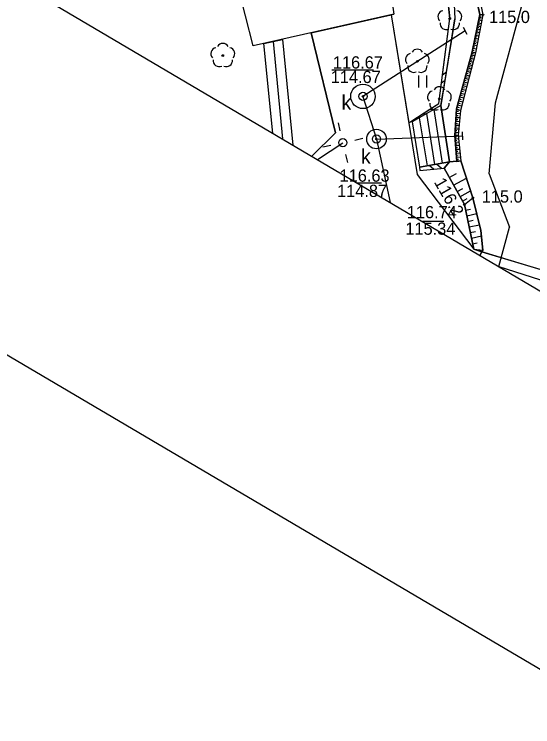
# Model space of a CAD drawing. Extents: x 6434771 to 6436222, y 5663454 to 5664782.
# Drawn here: x 6434897.1 to 6434928.91, y 5663961.14 to 5664004.88 of the extents above; entities that cross this region are included whole.
import ezdxf

# ---------------------------------------------------------------- set-up
doc = ezdxf.new("R2010")
doc.units = 0
for name, color, linetype in [('Warstwa 1', 7, 'Continuous'), ('Warstwa 11', 7, 'Continuous'), ('Warstwa 12', 7, 'Continuous'), ('Warstwa 13', 7, 'Continuous'), ('Warstwa 14', 7, 'Continuous'), ('Warstwa 15', 7, 'Continuous'), ('Warstwa 2', 7, 'Continuous'), ('Warstwa 20', 7, 'Continuous'), ('Warstwa 21', 7, 'Continuous'), ('Warstwa 36', 7, 'Continuous'), ('Warstwa 4', 7, 'Continuous'), ('Warstwa 5', 7, 'Continuous'), ('Warstwa 51', 7, 'Continuous'), ('Warstwa 6', 7, 'Continuous'), ('Warstwa 63', 7, 'Continuous'), ('Warstwa 7', 7, 'Continuous'), ('Warstwa 8', 7, 'Continuous'), ('Warstwa 9', 7, 'Continuous')]:
    doc.layers.add(name, color=color, linetype=linetype)

msp = doc.modelspace()

# ---------------------------------------------------------------- linework, layer by layer
at = {"layer": 'Warstwa 1'}
for p, q in [((6434926.635, 5663999.433), (6434928.362, 5664005.889)), ((6434926.235, 5663995.079), (6434926.635, 5663999.433)), ((6434926.235, 5663995.079), (6434927.494, 5663991.812)), ((6434926.828, 5663989.395), (6434927.494, 5663991.812))]:
    msp.add_line(p, q, dxfattribs=at)
msp.add_lwpolyline([(6434911.812, 5664031.828), (6434920.38, 5664029.894), (6434918.982, 5664020.154), (6434921.832, 5664020.166), (6434921.856, 5664014.645), (6434919.005, 5664014.634), (6434920.397, 5664004.883), (6434911.753, 5664002.928), (6434910.828, 5664006.639), (6434910.117, 5664010.758), (6434909.494, 5664014.626), (6434909.488, 5664017.416), (6434909.44, 5664020.046), (6434910.163, 5664023.638), (6434910.979, 5664028.218)], close=True, dxfattribs=at)
at = {"layer": 'Warstwa 11'}
msp.add_lwpolyline([(6434925.122, 5664008.575), (6434925.857, 5664004.846), (6434925.409, 5664002.512), (6434924.476, 5663998.973), (6434924.338, 5663997.464), (6434924.499, 5663995.882), (6434925.241, 5663993.613), (6434925.737, 5663991.597), (6434925.843, 5663990.406), (6434925.787, 5663990.299), (6434925.671, 5663990.077)], dxfattribs=at)
for centre in [(6434923.824, 5664004.611), (6434909.896, 5664002.34), (6434921.832, 5664001.985), (6434923.185, 5663999.678)]:
    msp.add_circle(centre, 0.05, dxfattribs=at)
for centre, start, end in [((6434923.467, 5664004.727), 102.1471, 221.8529), ((6434924.181, 5664004.727), 318.1471, 77.8529), ((6434923.604, 5664004.308), 174.1471, 293.8529), ((6434924.044, 5664004.308), 246.1471, 5.8529), ((6434909.896, 5664002.715), 30.1471, 149.8529), ((6434909.539, 5664002.456), 102.1471, 221.8529), ((6434910.253, 5664002.456), 318.1471, 77.8529), ((6434921.832, 5664002.36), 30.1471, 149.8529), ((6434909.676, 5664002.037), 174.1471, 293.8529), ((6434910.116, 5664002.037), 246.1471, 5.8529), ((6434921.475, 5664002.101), 102.1471, 221.8529), ((6434922.189, 5664002.101), 318.1471, 77.8529), ((6434921.612, 5664001.682), 174.1471, 293.8529), ((6434922.052, 5664001.682), 246.1471, 5.8529), ((6434923.185, 5664000.053), 30.1471, 149.8529), ((6434922.828, 5663999.794), 102.1471, 221.8529), ((6434923.542, 5663999.794), 318.1471, 77.8529), ((6434922.965, 5663999.375), 174.1471, 293.8529), ((6434923.405, 5663999.375), 246.1471, 5.8529)]:
    msp.add_arc(centre, 0.375, start, end, dxfattribs=at)
at = {"layer": 'Warstwa 12'}
for points in [[(6434912.982, 5664003.206), (6434913.556, 5663997.226)], [(6434915.706, 5663995.958), (6434917.262, 5663996.99)]]:
    msp.add_lwpolyline(points, dxfattribs=at)
at = {"layer": 'Warstwa 13'}
for centre in [(6434925.857, 5664004.846), (6434925.241, 5663993.613), (6434924.716, 5663993.19)]:
    msp.add_circle(centre, 0.045, dxfattribs=at)
at = {"layer": 'Warstwa 14'}
for p, q in [((6434919.142, 5664001.452), (6434916.593, 5664001.452)), ((6434919.641, 5663994.508), (6434918.162, 5663994.508)), ((6434923.463, 5663992.147), (6434922.164, 5663992.147))]:
    msp.add_line(p, q, dxfattribs=at)
for centre in [(6434918.496, 5663999.835), (6434919.324, 5663997.215)]:
    msp.add_circle(centre, 0.045, dxfattribs=at)
at = {"layer": 'Warstwa 15'}
for centre, radius in [((6434918.496, 5663999.835), 0.75), ((6434919.324, 5663997.215), 0.6)]:
    msp.add_circle(centre, radius, dxfattribs=at)
at = {"layer": 'Warstwa 2'}
for points in [[(6434920.236, 5664004.847), (6434921.818, 5663995.035), (6434925.293, 5663990.452), (6434938.635, 5663986.4)], [(6434915.352, 5663996.166), (6434916.809, 5663997.596), (6434915.318, 5664003.734)]]:
    msp.add_lwpolyline(points, dxfattribs=at)
msp.add_circle((6434917.262, 5663996.99), 0.25, dxfattribs=at)
at = {"layer": 'Warstwa 20'}
for p, q in [((6434924.889, 5664003.626), (6434924.661, 5664004.072)), ((6434924.618, 5663997.161), (6434924.596, 5663997.661))]:
    msp.add_line(p, q, dxfattribs=at)
for points in [[(6434925.546, 5664033.621), (6434924.451, 5664030.734), (6434923.907, 5664028.791), (6434923.383, 5664023.537), (6434924.334, 5664011.185), (6434924.872, 5664008.518), (6434925.668, 5664004.869), (6434925.2, 5664002.574), (6434924.237, 5663999.066), (6434924.128, 5663997.437), (6434924.248, 5663995.845)], [(6434925.293, 5663990.452), (6434924.716, 5663993.19), (6434923.473, 5663995.425)]]:
    msp.add_lwpolyline(points, dxfattribs=at)
at = {"layer": 'Warstwa 21'}
for points in [[(6434925.755, 5664033.559), (6434924.242, 5664028.377), (6434923.988, 5664023.91), (6434923.741, 5664023.373), (6434924.496, 5664011.353), (6434925.122, 5664008.575), (6434925.857, 5664004.846), (6434925.409, 5664002.512), (6434924.476, 5663998.973), (6434924.338, 5663997.464), (6434924.499, 5663995.882)], [(6434924.499, 5663995.882), (6434925.241, 5663993.613), (6434925.737, 5663991.597), (6434925.843, 5663990.406), (6434925.787, 5663990.299)]]:
    msp.add_lwpolyline(points, dxfattribs=at)
at = {"layer": 'Warstwa 36'}
for p, q in [((6434922.837, 5663999.028), (6434923.347, 5663995.736)), ((6434922.394, 5663998.778), (6434922.886, 5663995.652)), ((6434921.951, 5663998.528), (6434922.425, 5663995.567))]:
    msp.add_line(p, q, dxfattribs=at)
msp.add_lwpolyline([(6434923.28, 5663999.277), (6434921.508, 5663998.279), (6434921.964, 5663995.483), (6434923.808, 5663995.821), (6434923.28, 5663999.277)], dxfattribs=at)
at = {"layer": 'Warstwa 4'}
for points in [[(6434917.096, 5663997.721), (6434916.986, 5663998.209)], [(6434917.993, 5663997.156), (6434918.481, 5663997.266)], [(6434916.531, 5663996.824), (6434916.043, 5663996.714)], [(6434917.428, 5663996.259), (6434917.538, 5663995.771)]]:
    msp.add_lwpolyline(points, dxfattribs=at)
for centre in [(6434918.496, 5663999.835), (6434919.324, 5663997.215)]:
    msp.add_circle(centre, 0.25, dxfattribs=at)
at = {"layer": 'Warstwa 5'}
for p, q in [((6434924.872, 5664008.518), (6434925.668, 5664004.869)), ((6434924.041, 5664006.623), (6434924.134, 5664004.587)), ((6434923.661, 5664006.154), (6434923.824, 5664004.611)), ((6434920.236, 5664004.847), (6434920.397, 5664004.883)), ((6434920.236, 5664004.847), (6434921.307, 5663998.202)), ((6434925.2, 5664002.574), (6434925.668, 5664004.869)), ((6434923.371, 5664001.151), (6434923.824, 5664004.611)), ((6434923.611, 5664001.335), (6434924.134, 5664004.587)), ((6434924.237, 5663999.066), (6434925.2, 5664002.574)), ((6434923.53, 5664000.832), (6434923.611, 5664001.335)), ((6434921.916, 5664000.371), (6434921.916, 5664001.121)), ((6434922.416, 5664000.371), (6434922.416, 5664001.121)), ((6434923.28, 5663999.277), (6434923.53, 5664000.832)), ((6434923.306, 5664000.66), (6434923.371, 5664001.151)), ((6434923.141, 5663999.399), (6434923.306, 5664000.66)), ((6434921.488, 5663998.339), (6434922.608, 5663999.057)), ((6434922.608, 5663999.057), (6434923.141, 5663999.399)), ((6434923.28, 5663999.277), (6434923.808, 5663995.821)), ((6434924.128, 5663997.437), (6434924.237, 5663999.066)), ((6434921.307, 5663998.202), (6434921.488, 5663998.339)), ((6434924.128, 5663997.437), (6434924.247, 5663995.86)), ((6434923.808, 5663995.821), (6434924.247, 5663995.86))]:
    msp.add_line(p, q, dxfattribs=at)
at = {"layer": 'Warstwa 51'}
for p, q in [((6434923.37, 5664001.151), (6434923.611, 5664001.335)), ((6434923.306, 5664000.66), (6434923.53, 5664000.832)), ((6434922.608, 5663999.057), (6434922.811, 5663999.013)), ((6434922.192, 5663998.789), (6434922.352, 5663998.755)), ((6434922.824, 5663995.363), (6434922.549, 5663995.59)), ((6434923.317, 5663995.41), (6434922.999, 5663995.673))]:
    msp.add_line(p, q, dxfattribs=at)
for points in [[(6434921.488, 5663998.339), (6434923.141, 5663999.399), (6434923.824, 5664004.611), (6434923.142, 5664011.06), (6434923.107, 5664014.77), (6434922.7, 5664021.635), (6434922.646, 5664022.146), (6434922.795, 5664023.654), (6434923.613, 5664011.124), (6434923.952, 5664008.56), (6434924.134, 5664004.587), (6434923.28, 5663999.277), (6434921.508, 5663998.279), (6434921.488, 5663998.339)], [(6434923.473, 5663995.425), (6434923.808, 5663995.821), (6434921.964, 5663995.483), (6434921.981, 5663995.283), (6434923.473, 5663995.425)]]:
    msp.add_lwpolyline(points, dxfattribs=at)
at = {"layer": 'Warstwa 6'}
for centre in [(6434918.496, 5663999.835), (6434919.324, 5663997.215)]:
    msp.add_circle(centre, 0.045, dxfattribs=at)
at = {"layer": 'Warstwa 63'}
for points in [[(6434770.578, 5664058.35), (6435197.816, 5664782.406), (6436221.837, 5664178.169), (6435794.599, 5663454.114)], [(6435677.2, 5663546.629), (6436084.093, 5664236.205), (6435222.122, 5664744.822), (6434815.229, 5664055.245)]]:
    msp.add_lwpolyline(points, close=True, dxfattribs=at)
at = {"layer": 'Warstwa 7'}
for points in [[(6434924.775, 5664003.849), (6434918.496, 5663999.835), (6434919.324, 5663997.215)], [(6434919.324, 5663997.215), (6434924.607, 5663997.411)], [(6434919.324, 5663997.215), (6434920.162, 5663993.328)]]:
    msp.add_lwpolyline(points, dxfattribs=at)
at = {"layer": 'Warstwa 8'}
for points in [[(6434912.957, 5663997.579), (6434912.407, 5664003.076), (6434913.558, 5664003.336), (6434914.203, 5663996.844)], [(6434926.834, 5663989.391), (6434930.863, 5663988.105), (6434943.667, 5663984.044), (6434942.349, 5663980.236)]]:
    msp.add_lwpolyline(points, dxfattribs=at)
at = {"layer": 'Warstwa 9'}
for p, q in [((6434915.318, 5664003.734), (6434920.236, 5664004.847)), ((6434920.236, 5664004.847), (6434921.818, 5663995.035)), ((6434925.633, 5664004.698), (6434925.821, 5664004.66)), ((6434925.651, 5664004.784), (6434925.744, 5664004.765)), ((6434925.857, 5664004.846), (6434925.668, 5664004.869)), ((6434925.668, 5664004.869), (6434925.857, 5664004.846)), ((6434925.543, 5664004.256), (6434925.64, 5664004.237)), ((6434925.561, 5664004.347), (6434925.754, 5664004.307)), ((6434925.579, 5664004.436), (6434925.675, 5664004.416)), ((6434925.597, 5664004.524), (6434925.788, 5664004.485)), ((6434925.616, 5664004.611), (6434925.71, 5664004.592)), ((6434925.448, 5664003.791), (6434925.647, 5664003.751)), ((6434925.468, 5664003.887), (6434925.567, 5664003.867)), ((6434925.487, 5664003.981), (6434925.683, 5664003.94)), ((6434925.506, 5664004.073), (6434925.604, 5664004.053)), ((6434925.524, 5664004.165), (6434925.719, 5664004.126)), ((6434915.318, 5664003.734), (6434916.809, 5663997.596)), ((6434925.369, 5664003.402), (6434925.572, 5664003.361)), ((6434925.389, 5664003.501), (6434925.49, 5664003.481)), ((6434925.409, 5664003.599), (6434925.61, 5664003.558)), ((6434925.428, 5664003.695), (6434925.528, 5664003.675)), ((6434925.286, 5664002.997), (6434925.494, 5664002.955)), ((6434925.307, 5664003.1), (6434925.411, 5664003.079)), ((6434925.327, 5664003.202), (6434925.534, 5664003.159)), ((6434925.349, 5664003.302), (6434925.45, 5664003.281)), ((6434925.174, 5664002.479), (6434925.279, 5664002.45)), ((6434925.2, 5664002.574), (6434925.409, 5664002.512)), ((6434925.222, 5664002.681), (6434925.328, 5664002.66)), ((6434925.243, 5664002.788), (6434925.454, 5664002.745)), ((6434925.265, 5664002.892), (6434925.369, 5664002.871)), ((6434925.067, 5664002.091), (6434925.175, 5664002.061)), ((6434925.094, 5664002.189), (6434925.308, 5664002.131)), ((6434925.121, 5664002.287), (6434925.228, 5664002.258)), ((6434925.148, 5664002.384), (6434925.36, 5664002.325)), ((6434924.957, 5664001.687), (6434925.067, 5664001.658)), ((6434924.984, 5664001.79), (6434925.203, 5664001.73)), ((6434925.013, 5664001.891), (6434925.121, 5664001.861)), ((6434925.04, 5664001.991), (6434925.256, 5664001.931)), ((6434924.813, 5664001.163), (6434925.037, 5664001.101)), ((6434924.842, 5664001.269), (6434924.954, 5664001.239)), ((6434924.871, 5664001.375), (6434925.094, 5664001.314)), ((6434924.9, 5664001.481), (6434925.01, 5664001.45)), ((6434924.928, 5664001.584), (6434925.149, 5664001.524)), ((6434924.692, 5664000.725), (6434924.922, 5664000.662)), ((6434924.723, 5664000.837), (6434924.837, 5664000.805)), ((6434924.753, 5664000.946), (6434924.98, 5664000.884)), ((6434924.783, 5664001.055), (6434924.896, 5664001.024)), ((6434924.6, 5664000.387), (6434924.716, 5664000.356)), ((6434924.631, 5664000.501), (6434924.862, 5664000.437)), ((6434924.662, 5664000.614), (6434924.777, 5664000.582)), ((6434924.473, 5663999.922), (6434924.59, 5663999.889)), ((6434924.504, 5664000.039), (6434924.74, 5663999.975)), ((6434924.537, 5664000.157), (6434924.654, 5664000.125)), ((6434924.568, 5664000.273), (6434924.802, 5664000.209)), ((6434924.34, 5663999.439), (6434924.46, 5663999.406)), ((6434924.373, 5663999.562), (6434924.615, 5663999.496)), ((6434924.407, 5663999.683), (6434924.526, 5663999.65)), ((6434924.439, 5663999.803), (6434924.677, 5663999.737)), ((6434924.237, 5663999.066), (6434924.476, 5663998.973)), ((6434924.272, 5663999.192), (6434924.394, 5663999.159)), ((6434924.306, 5663999.316), (6434924.55, 5663999.249)), ((6434924.202, 5663998.546), (6434924.436, 5663998.53)), ((6434924.211, 5663998.671), (6434924.328, 5663998.664)), ((6434924.219, 5663998.799), (6434924.459, 5663998.783)), ((6434924.229, 5663998.93), (6434924.35, 5663998.922)), ((6434924.178, 5663998.187), (6434924.291, 5663998.18)), ((6434924.186, 5663998.304), (6434924.414, 5663998.288)), ((6434924.195, 5663998.423), (6434924.309, 5663998.416)), ((6434924.148, 5663997.745), (6434924.255, 5663997.737)), ((6434924.156, 5663997.852), (6434924.372, 5663997.837)), ((6434924.163, 5663997.96), (6434924.273, 5663997.953)), ((6434924.17, 5663998.072), (6434924.392, 5663998.058)), ((6434915.352, 5663996.166), (6434916.809, 5663997.596)), ((6434924.128, 5663997.437), (6434924.338, 5663997.464)), ((6434924.135, 5663997.538), (6434924.239, 5663997.531)), ((6434924.135, 5663997.338), (6434924.242, 5663997.346)), ((6434924.141, 5663997.64), (6434924.353, 5663997.625)), ((6434924.143, 5663997.238), (6434924.359, 5663997.254)), ((6434924.151, 5663997.135), (6434924.26, 5663997.143)), ((6434924.159, 5663997.031), (6434924.38, 5663997.047)), ((6434924.166, 5663996.923), (6434924.278, 5663996.932)), ((6434924.175, 5663996.813), (6434924.402, 5663996.831)), ((6434924.184, 5663996.702), (6434924.299, 5663996.711)), ((6434924.192, 5663996.587), (6434924.426, 5663996.604)), ((6434924.201, 5663996.47), (6434924.319, 5663996.48)), ((6434924.21, 5663996.351), (6434924.45, 5663996.369)), ((6434924.219, 5663996.229), (6434924.34, 5663996.238)), ((6434924.228, 5663996.104), (6434924.475, 5663996.123)), ((6434924.239, 5663995.976), (6434924.363, 5663995.986)), ((6434924.499, 5663995.882), (6434923.808, 5663995.821)), ((6434924.248, 5663995.845), (6434924.499, 5663995.882)), ((6434923.792, 5663994.851), (6434924.234, 5663995.096)), ((6434921.818, 5663995.035), (6434925.293, 5663990.452)), ((6434924.055, 5663994.379), (6434924.847, 5663994.819)), ((6434924.271, 5663993.99), (6434924.629, 5663994.19)), ((6434924.449, 5663993.67), (6434925.103, 5663994.034)), ((6434924.596, 5663993.406), (6434924.898, 5663993.573)), ((6434924.716, 5663993.19), (6434925.241, 5663993.613)), ((6434924.788, 5663992.849), (6434925.093, 5663992.913)), ((6434924.86, 5663992.507), (6434925.482, 5663992.637)), ((6434924.933, 5663992.164), (6434925.249, 5663992.231)), ((6434925.005, 5663991.822), (6434925.648, 5663991.957)), ((6434925.077, 5663991.479), (6434925.404, 5663991.548)), ((6434925.148, 5663991.137), (6434925.766, 5663991.268)), ((6434925.221, 5663990.794), (6434925.509, 5663990.855)), ((6434925.293, 5663990.452), (6434925.843, 5663990.406)), ((6434925.293, 5663990.452), (6434925.788, 5663990.302)), ((6434925.67, 5663990.078), (6434925.788, 5663990.302)), ((6434925.671, 5663990.077), (6434925.787, 5663990.299)), ((6434925.787, 5663990.299), (6434938.424, 5663986.464))]:
    msp.add_line(p, q, dxfattribs=at)
for points in [[(6434924.248, 5663995.845), (6434924.128, 5663997.437), (6434924.237, 5663999.066), (6434925.2, 5664002.574), (6434925.668, 5664004.869), (6434924.872, 5664008.518), (6434924.334, 5664011.185), (6434923.383, 5664023.537), (6434923.907, 5664028.791), (6434924.451, 5664030.734), (6434925.546, 5664033.621), (6434925.755, 5664033.559), (6434924.242, 5664028.377), (6434923.988, 5664023.91), (6434923.741, 5664023.373), (6434924.496, 5664011.353), (6434925.122, 5664008.575), (6434925.857, 5664004.846), (6434925.409, 5664002.512), (6434924.476, 5663998.973), (6434924.338, 5663997.464), (6434924.499, 5663995.882)], [(6434925.787, 5663990.299), (6434925.843, 5663990.406), (6434925.737, 5663991.597), (6434925.241, 5663993.613), (6434924.499, 5663995.882), (6434923.808, 5663995.821), (6434923.473, 5663995.425), (6434924.716, 5663993.19), (6434925.293, 5663990.452)]]:
    msp.add_lwpolyline(points, close=True, dxfattribs=at)

# ---------------------------------------------------------------- texts
at = {"layer": 'Warstwa 13'}
for p in [(6434926.228, 5664004.337), (6434925.785, 5663993.315)]:
    msp.add_text('115.0', height=0.75, dxfattribs=at).set_placement(p)
msp.add_text('116.2', height=0.75, rotation=299.7715, dxfattribs=at).set_placement((6434922.833, 5663994.576))
at = {"layer": 'Warstwa 14'}
for s, p in [('114.67', (6434916.519, 5664000.654)), ('114.87', (6434916.908, 5663993.66)), ('115.34', (6434921.097, 5663991.343))]:
    msp.add_text(s, height=0.75, dxfattribs=at).set_placement(p)
at = {"layer": 'Warstwa 5'}
for p in [(6434917.179, 5663999.014), (6434918.37, 5663995.703)]:
    msp.add_text('k', height=0.9, dxfattribs=at).set_placement(p)
at = {"layer": 'Warstwa 6'}
for s, p in [('116.67', (6434916.65, 5664001.545)), ('116.63', (6434917.061, 5663994.598)), ('116.74', (6434921.186, 5663992.356))]:
    msp.add_text(s, height=0.75, dxfattribs=at).set_placement(p)

doc.saveas('drawing.dxf')
